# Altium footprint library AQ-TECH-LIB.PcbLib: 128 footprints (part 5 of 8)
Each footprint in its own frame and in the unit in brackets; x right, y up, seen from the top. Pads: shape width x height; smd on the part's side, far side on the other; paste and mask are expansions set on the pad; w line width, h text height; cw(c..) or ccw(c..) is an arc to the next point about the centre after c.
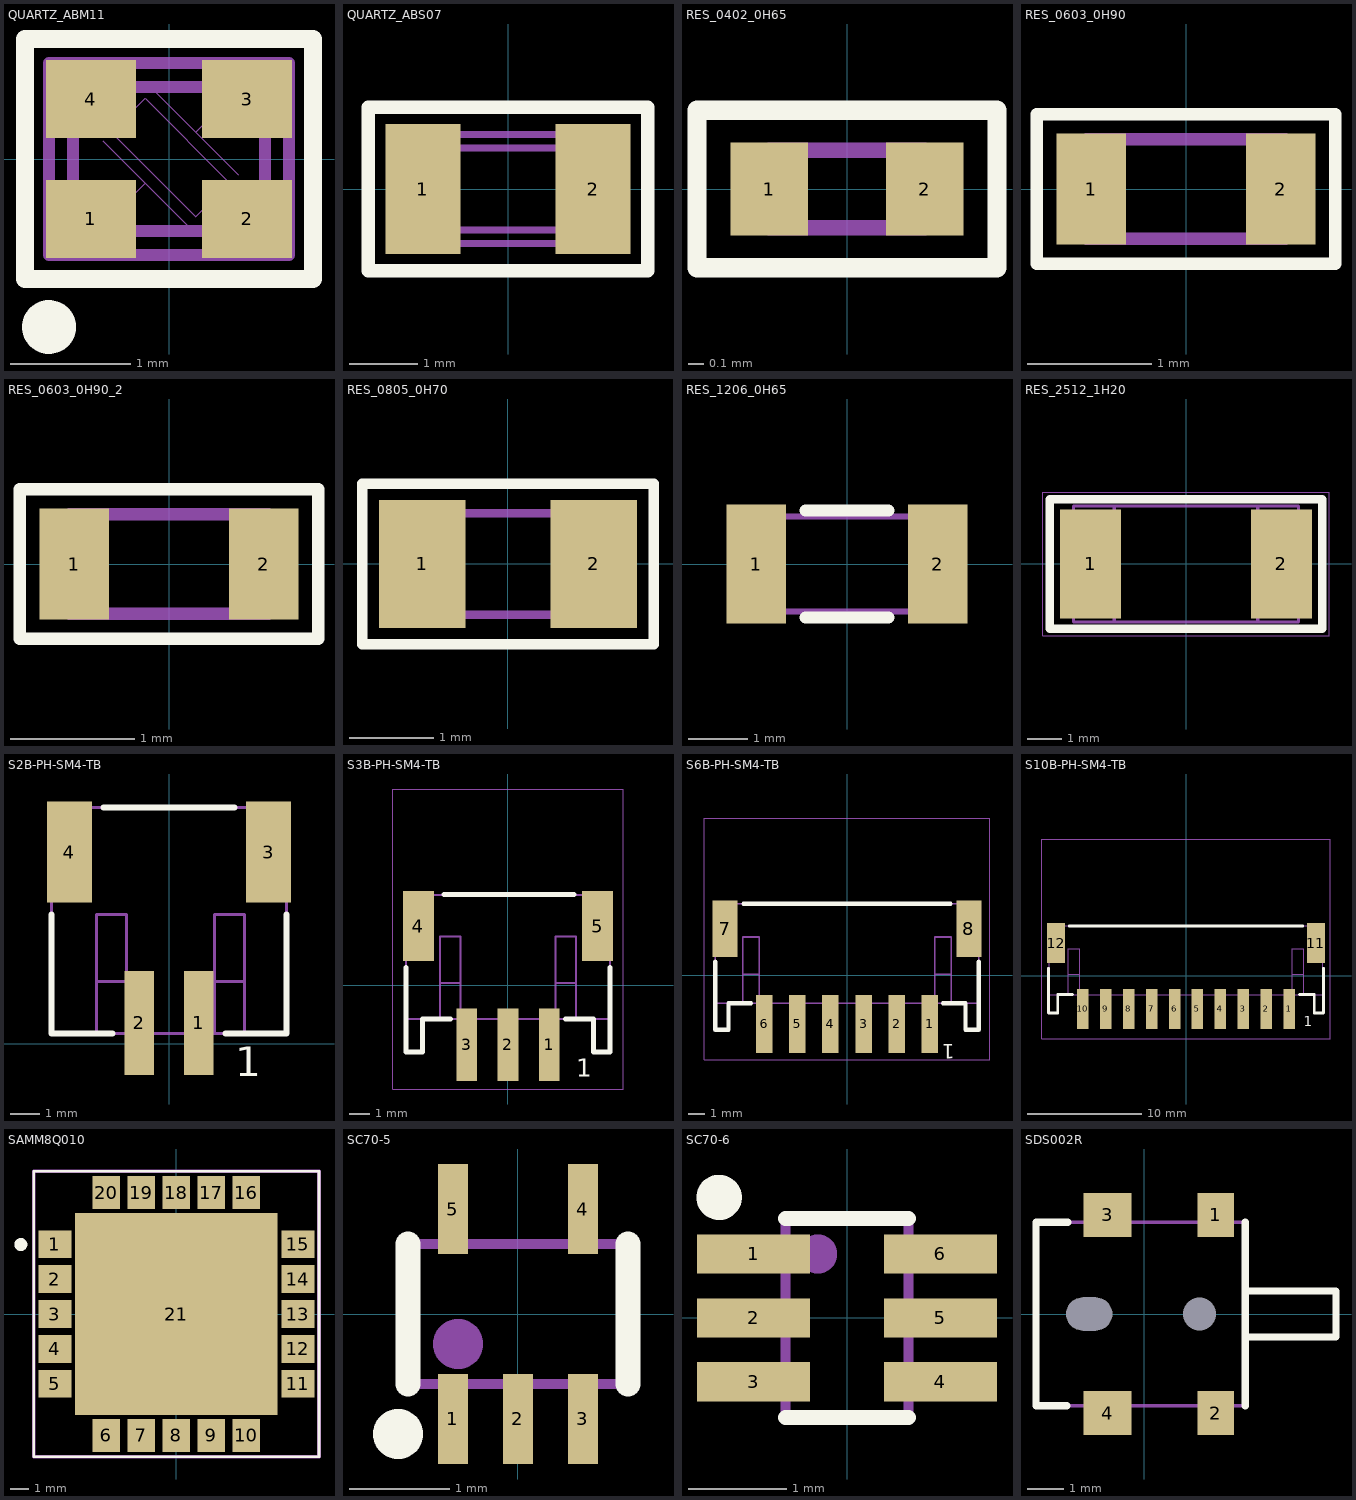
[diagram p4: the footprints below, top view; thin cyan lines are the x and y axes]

## QUARTZ_ABM11 [mm]
height 0.6
pads (4):
  rect 0.75x0.65 smd paste+0 mask+0.1: 1(-0.65,-0.5) 2(0.65,-0.5) 3(0.65,0.5) 4(-0.65,0.5)
Top Overlay:
  circle w0.25: c-1,-1.4 r0.1
  lines w0.15: -1.2,-1 1.2,-1 1.2,1 -1.2,1 -1.2,-1
Mechanical 3:
  lines w0.01: -0.554,-0.554 -0.2,-0.2 ; -0.554,0.154 0.154,-0.554 ; -0.129,0.578 0.578,-0.129 ; 0.224,0.224 0.578,0.578 ; -0.483,0.224 -0.2,0.507 0.507,-0.2 0.224,-0.483 -0.483,0.224
  lines w0.1: -1,-0.8 1,-0.8 1,0.8 -1,0.8 -1,-0.8 ; -0.8,-0.6 0.8,-0.6 0.8,0.6 -0.8,0.6 -0.8,-0.6
  text ".Designator" at -0.6,-0.1 h0.84
3D body "ABM11.STEP": height 0.59, standoff 0, extent -1.003,-0.8 1.003,0.8

## QUARTZ_ABS07 [mm]
height 0.9
pads (2):
  rect 1.1x1.9 smd paste+0 mask+0.1: 1(-1.25,0) 2(1.25,0)
Top Overlay:
  lines w0.2: -2.05,-1.2 2.05,-1.2 2.05,1.2 -2.05,1.2 -2.05,-1.2
Mechanical 3:
  lines w0.1: -1.6,-0.6 cw(c-1.55,-0.75) -1.4,-0.8 1.4,-0.8 cw(c1.55,-0.75) 1.6,-0.6 1.6,0.6 cw(c1.55,0.75) 1.4,0.8 -1.4,0.8 cw(c-1.55,0.75) -1.6,0.6 -1.6,-0.6 ; -1.4,-0.3 ccw(c-1.1,-0.3) -1.1,-0.6 1.1,-0.6 ccw(c1.1,-0.3) 1.4,-0.3 1.4,0.3 ccw(c1.1,0.3) 1.1,0.6 -1.1,0.6 ccw(c-1.1,0.3) -1.4,0.3 -1.4,-0.3
  text ".Designator" at -0.775,-0.15 h0.84
3D body "ABS07.STEP": height 0.89, standoff 0, extent -1.6,-0.749 1.6,0.749

## RES_0402_0H65 [mm]
height 0.65
pads (2):
  rect 0.5x0.6 smd: 1(-0.5,0) 2(0.5,0)
Top Overlay:
  lines w0.125: -0.965,-0.508 0.965,-0.508 0.965,0.508 -0.965,0.508 -0.965,-0.508
Mechanical 3:
  lines w0.1: -0.5,-0.25 -0.5,0.25 0.5,0.25 0.5,-0.25 -0.5,-0.25
  text "'.Designator'" at -0.965,0.508 h1
3D body: height 0.65, standoff 0, extent -0.5,-0.25 0.5,0.25

## RES_0603_0H90 [mil]
height 35.43
pads (2):
  rect 22x35 smd: 1(-30,0) 2(30,0)
Top Overlay:
  lines w3.94: -47.24,-23.62 -47.24,23.62 47.24,23.62 47.24,-23.62 -47.24,-23.62
Mechanical 3:
  lines w3.94: -31.5,-15.75 31.5,-15.75 31.5,15.75 -31.5,15.75 -31.5,-15.75
  text "'.Designator'" at 137.8,15.75 h31.5
3D body: height 35.43, standoff 0, extent -31.5,-15.75 31.5,15.75

## RES_0603_0H90_2 [mil]
pads (2):
  rect 22x35 smd: 1(-30,0) 2(30,0)
Top Overlay:
  lines w3.94: -47.24,-23.62 -47.24,23.62 47.24,23.62 47.24,-23.62 -47.24,-23.62
Mechanical 3:
  lines w3.94: -31.5,-15.75 31.5,-15.75 31.5,15.75 -31.5,15.75 -31.5,-15.75
  text "'.Designator'" at -90.55,-3.94 h23.62
3D body: height 35.43, standoff 0, extent -31.5,-15.75 31.5,15.75

## RES_0805_0H70 [mm] "refusion"
height 0.7
pads (2):
  rect 1.02x1.52 smd: 1(-1.016,0) 2(1.016,0)
Top Overlay:
  lines w0.125: -1.725,-0.95 -1.725,0.95 1.725,0.95 1.725,-0.95 -1.725,-0.95
Mechanical 3:
  lines w0.1: -1,-0.6 -1,0.6 1,0.6 1,-0.6 -1,-0.6
  text ".Designator" at -0.7,-0.4 h0.84
3D body: height 0.7, standoff 0, extent -1.525,-0.7 1.475,0.725

## RES_1206_0H65 [mm] "refusion"
height 0.65
pads (2):
  rect 1x2 smd paste+0 mask+0.1: 1(-1.524,0) 2(1.524,0)
Top Overlay:
  lines w0.2: -0.7,-0.9 0.7,-0.9 ; -0.7,0.9 0.7,0.9
Mechanical 3:
  lines w0.1: -1.6,-0.8 1.6,-0.8 1.6,0.8 -1.6,0.8 -1.6,-0.8
  text ".Designator" at -1,-0.375 h0.84
3D body: height 0.65, standoff 0, extent -1.75,-0.9 1.75,0.9

## RES_2512_1H20 [mm]
height 1.2
pads (2):
  rect 1.8x3.2 smd paste+0 mask+0.1: 1(-2.8,0) 2(2.8,0)
Top Overlay:
  lines w0.25: -4,-1.9 -4,1.9 4,1.9 4,-1.9 -4,-1.9
Mechanical 2:
  lines w0.01: -4.2,-2.1 -4.2,2.1 4.2,2.1 4.2,-2.1 -4.2,-2.1
Mechanical 3:
  lines w0.1: -3.3,-1.7 -3.3,1.7 ; -3.3,-1.7 -2.1,-1.7 -2.1,1.7 -3.3,1.7 ; -3.3,-1.7 -3.3,1.7 ; -3.3,-1.7 3.3,-1.7 ; -3.3,1.7 3.3,1.7 ; 3.3,-1.7 2.1,-1.7 2.1,1.7 3.3,1.7 ; 3.3,-1.7 3.3,1.7 ; 3.3,-1.7 3.3,1.7
  text ".Designator" at 0.45,0.375 h0.84
3D body: height 1.2, standoff 0, extent -3.3,-1.7 -2.1,1.7
3D body: height 1.2, standoff 0, extent -2.1,-1.7 2.1,1.7
3D body: height 1.2, standoff 0, extent 2.1,-1.7 3.3,1.7

## S2B-PH-SM4-TB [mm]
height 5.5
pads (4):
  rect 1x3.5 smd: 1(1,0.7) 2(-1,0.7)
  rect 1.5x3.4 smd: 3(3.35,6.45) 4(-3.35,6.45)
Top Overlay:
  lines w0.2: -3.95,4.35 -3.95,0.35 -1.9,0.35 ; -2.2,7.95 2.2,7.95 ; 1.9,0.35 3.95,0.35 3.95,4.35
  text "1" at 2.225,-1.1 h1
Mechanical 3:
  lines w0.1: -2.435,0.35 -2.435,4.35 -1.435,4.35 -1.435,0.35 ; -2.435,2.1 -1.435,2.1 ; 1.539,0.35 1.539,4.35 2.539,4.35 2.539,0.35 ; 1.539,2.1 2.539,2.1 ; -3.95,0.35 -3.95,7.95 3.95,7.95 3.95,0.35 -3.95,0.35
  text "1" at 3.075,0.725 h0.84
  text ".Designator" at -0.05,2.825 h0.84
3D body "S2B-PH-SM4-TB(LF)(SN)--3DModel-STEP-56544.STEP": height 5.58, standoff -0.02, extent -3.95,-0.65 3.95,7.95

## S3B-PH-SM4-TB [mm]
height 5.7
pads (5):
  rect 1x3.5 smd mask+0.1: 1(2,-2.875) 2(0,-2.875) 3(-2,-2.875)
  rect 1.5x3.4 smd mask+0.1: 4(-4.35,2.875) 5(4.35,2.875)
Top Overlay:
  lines w0.25: -4.95,0.875 -4.95,-3.225 -4.15,-3.225 -4.15,-1.625 -2.8,-1.625 ; -3.1,4.4 3.2,4.4 ; 2.8,-1.625 4.15,-1.625 4.15,-3.225 4.95,-3.225 4.95,0.875
  text "1" at 3.3,-4.725 h1.5
Mechanical 1:
  lines w0.01: -5.6,-5.025 5.6,-5.025 5.6,9.525 -5.6,9.525 -5.6,-5.025
Mechanical 3:
  lines w0.1: -4.45,3.575 -4.45,4.375 ; -4.15,-1.625 -4.15,-3.225 -4.95,-3.225 -4.95,-1.625 ; -3.3,0.125 -2.3,0.125 ; -0.25,-2.125 0.25,-2.125 ; -0.25,-1.625 -0.25,-2.225 ; 0.25,-1.625 0.25,-2.225 ; 1.75,-2.125 2.25,-2.125 ; 1.75,-1.625 1.75,-2.225 ; 2.25,-1.625 2.25,-2.225 ; 2.3,0.125 3.3,0.125 ; 4.15,-1.625 4.15,-3.225 4.95,-3.225 4.95,-1.625 ; 4.45,3.575 4.45,4.375 4.05,4.375 ; -4.95,-1.625 2.3,-1.625 ; -4.95,-1.625 -4.95,3.575 -4.05,3.575 -4.05,4.375 -4.45,4.375 ; -4.95,-1.625 -3.3,-1.625 ; -4.45,4.375 4.05,4.375 ; -3.3,-1.625 -2.3,-1.625 -2.3,2.375 -3.3,2.375 -3.3,-1.625 ; -2.25,-4.225 -2.25,-2.225 ; -2.25,-4.225 -1.75,-4.225 ; -2.25,-4.225 -1.75,-4.225 ; -2.25,-4.225 -2.25,-2.225 ; -2.25,-2.225 -1.75,-2.225 ; -2.25,-2.225 -1.75,-2.225 ; -2.25,-2.225 -2.25,-1.625 -2.25,-2.125 ; -2.25,-2.225 -2.25,-2.125 ; -2.25,-2.125 -1.75,-2.125 ; -2.25,-2.125 -1.75,-2.125 ; -1.75,-4.225 -1.75,-2.225 ; -1.75,-4.225 -1.75,-2.225 ; -1.75,-2.225 -1.75,-1.625 -1.75,-2.125 ; -1.75,-2.225 -1.75,-2.125 ; -0.25,-2.225 0.25,-2.225 ; -0.25,-2.225 -0.25,-4.225 0.25,-4.225 0.25,-2.225 ; 1.75,-2.225 2.25,-2.225 ; 1.75,-2.225 1.75,-4.225 2.25,-4.225 2.25,-2.225 ; 2.3,-1.625 3.3,-1.625 ; 2.3,-1.625 2.3,2.375 3.3,2.375 3.3,-1.625 ; 3.3,-1.625 4.95,-1.625 ; 4.05,4.375 4.05,3.575 4.95,3.575 4.95,-1.625
  text ".Designator" at 0,0 h0.84
  text "1" at 1.5,-1.375 h0.84
  text "3" at -1.9,-1.325 h0.84
3D body "S3B-PH-SM4-TB.STEP": height 5.6, standoff 0, extent -4.95,-4.225 4.95,4.375

## S6B-PH-SM4-TB [mm]
height 5.7
pads (8):
  rect 1x3.5 smd mask+0.1: 1(5,-2.95) 2(3,-2.95) 3(1,-2.95) 4(-1,-2.95) 5(-3,-2.95) 6(-5,-2.95)
  rect 1.5x3.4 smd mask+0.1: 7(-7.35,2.8) 8(7.35,2.8)
Top Overlay:
  lines w0.25: -7.95,0.8 -7.95,-3.3 -7.15,-3.3 -7.15,-1.7 -5.8,-1.7 ; -6.25,4.3 6.25,4.3 ; 5.8,-1.7 7.15,-1.7 7.15,-3.3 7.95,-3.3 7.95,0.8
  text "1" at 6.5,-3.884 h1.5
Mechanical 1:
  lines w0.01: -8.6,-5.1 8.6,-5.1 8.6,9.45 -8.6,9.45 -8.6,-5.1
Mechanical 3:
  lines w0.1: -7.45,3.5 -7.45,4.3 -7.05,4.3 ; -7.15,-1.7 -7.15,-3.3 -7.95,-3.3 -7.95,-1.7 ; -6.3,0.05 -5.3,0.05 ; -5.25,-1.7 -5.25,-2.2 ; -4.75,-1.7 -4.75,-2.2 ; -3.25,-2.2 -2.75,-2.2 ; -3.25,-1.7 -3.25,-2.3 ; -2.75,-1.7 -2.75,-2.3 ; -1.25,-2.2 -0.75,-2.2 ; -1.25,-1.7 -1.25,-2.3 ; -0.75,-1.7 -0.75,-2.3 ; 0.75,-2.2 1.25,-2.2 ; 0.75,-1.7 0.75,-2.3 ; 1.25,-1.7 1.25,-2.3 ; 2.75,-2.2 3.25,-2.2 ; 2.75,-1.7 2.75,-2.3 ; 3.25,-1.7 3.25,-2.3 ; 4.75,-2.2 5.25,-2.2 ; 4.75,-1.7 4.75,-2.3 ; 5.25,-1.7 5.25,-2.3 ; 5.3,0.05 6.3,0.05 ; 7.15,-1.7 7.15,-3.3 7.95,-3.3 7.95,-1.7 ; 7.45,3.5 7.45,4.3 7.05,4.3 ; -7.95,-1.7 -7.95,3.5 -7.05,3.5 -7.05,4.3 ; -7.95,-1.7 -6.3,-1.7 ; -7.05,4.3 7.05,4.3 ; -6.3,-1.7 -6.3,2.3 -5.3,2.3 -5.3,-1.7 ; -6.3,-1.7 -5.3,-1.7 ; -5.3,-1.7 5.3,-1.7 ; -5.25,-2.3 -4.75,-2.3 ; -5.25,-2.3 -5.25,-4.3 -4.75,-4.3 -4.75,-2.3 ; -5.25,-2.3 -5.25,-2.2 ; -5.25,-2.2 -4.75,-2.2 ; -4.75,-2.3 -4.75,-2.2 ; -3.25,-2.3 -3.25,-4.3 -2.75,-4.3 -2.75,-2.3 ; -3.25,-2.3 -2.75,-2.3 ; -1.25,-2.3 -0.75,-2.3 ; -1.25,-2.3 -1.25,-4.3 -0.75,-4.3 -0.75,-2.3 ; 0.75,-2.3 1.25,-2.3 ; 0.75,-2.3 0.75,-4.3 1.25,-4.3 1.25,-2.3 ; 2.75,-2.3 3.25,-2.3 ; 2.75,-2.3 2.75,-4.3 3.25,-4.3 3.25,-2.3 ; 4.75,-2.3 5.25,-2.3 ; 4.75,-2.3 4.75,-4.3 5.25,-4.3 5.25,-2.3 ; 5.3,-1.7 5.3,2.3 6.3,2.3 6.3,-1.7 ; 5.3,-1.7 6.3,-1.7 ; 6.3,-1.7 7.95,-1.7 ; 7.05,4.3 7.05,3.5 7.95,3.5 7.95,-1.7
  text ".Designator" at -0.4,1.455 h0.84
  text "1" at 4.5,-0.5 h0.84
  text "6" at -4.1,-0.3 h0.84
3D body "S6B-PH-SM4-TB.STEP": height 5.6, standoff 0, extent -7.95,-4.3 7.95,4.3

## S10B-PH-SM4-TB [mm]
height 5.7
pads (12):
  rect 1x3.5 smd mask+0.1: 1(9,-2.875) 2(7,-2.875) 3(5,-2.875) 4(3,-2.875) 5(1,-2.875) 6(-1,-2.875) 7(-3,-2.875) 8(-5,-2.875) 9(-7,-2.875) 10(-9,-2.875)
  rect 1.6x3.5 smd mask+0.1: 11(11.35,2.875) 12(-11.35,2.875)
Top Overlay:
  lines w0.25: -12,0.675 -12,-3.225 -11.2,-3.225 -11.2,-1.625 -9.9,-1.625 ; -10.2,4.375 10.2,4.375 ; 9.9,-1.625 11.2,-1.625 11.2,-3.225 12,-3.225 12,0.675
  text "1" at 10.3,-4.7 h1.5
Mechanical 1:
  lines w0.01: -12.6,-5.475 12.6,-5.475 12.6,11.925 -12.6,11.925 -12.6,-5.475
Mechanical 3:
  lines w0.1: -11.45,3.575 -11.45,4.375 -11.05,4.375 ; -11.15,-1.625 -11.15,-3.225 -11.95,-3.225 -11.95,-1.625 ; -10.3,0.125 -9.3,0.125 ; -9.25,-1.625 -9.25,-2.125 ; -8.75,-1.625 -8.75,-2.125 ; -7.25,-1.625 -7.25,-2.125 ; -6.75,-1.625 -6.75,-2.125 ; -5.25,-1.625 -5.25,-2.125 ; -4.75,-1.625 -4.75,-2.125 ; -3.25,-1.625 -3.25,-2.125 ; -2.75,-1.625 -2.75,-2.125 ; -0.75,-1.625 -0.75,-2.125 ; 0.75,-2.125 1.25,-2.125 ; 0.75,-1.625 0.75,-2.225 ; 1.25,-1.625 1.25,-2.225 ; 2.75,-2.125 3.25,-2.125 ; 2.75,-1.625 2.75,-2.225 ; 3.25,-1.625 3.25,-2.225 ; 4.75,-2.125 5.25,-2.125 ; 4.75,-1.625 4.75,-2.225 ; 5.25,-1.625 5.25,-2.225 ; 6.75,-2.125 7.25,-2.125 ; 6.75,-1.625 6.75,-2.225 ; 7.25,-1.625 7.25,-2.225 ; 8.75,-2.125 9.25,-2.125 ; 8.75,-1.625 8.75,-2.225 ; 9.25,-1.625 9.25,-2.225 ; 9.3,0.125 10.3,0.125 ; 11.15,-1.625 11.15,-3.225 11.95,-3.225 11.95,-1.625 ; 11.45,3.575 11.45,4.375 11.05,4.375 ; -11.95,-1.625 -11.95,3.575 -11.05,3.575 -11.05,4.375 ; -11.95,-1.625 -10.3,-1.625 ; -11.05,4.375 11.05,4.375 ; -10.3,-1.625 -10.3,2.375 -9.3,2.375 -9.3,-1.625 ; -10.3,-1.625 -9.3,-1.625 ; -9.3,-1.625 -1.25,-1.625 ; -9.25,-2.225 -9.25,-2.125 ; -9.25,-2.225 -8.75,-2.225 ; -9.25,-2.225 -9.25,-4.225 -8.75,-4.225 -8.75,-2.225 ; -9.25,-2.125 -8.75,-2.125 ; -8.75,-2.225 -8.75,-2.125 ; -7.25,-2.225 -6.75,-2.225 ; -7.25,-2.225 -7.25,-2.125 ; -7.25,-2.225 -7.25,-4.225 -6.75,-4.225 -6.75,-2.225 ; -7.25,-2.125 -6.75,-2.125 ; -6.75,-2.225 -6.75,-2.125 ; -5.25,-2.225 -5.25,-2.125 ; -5.25,-2.225 -4.75,-2.225 ; -5.25,-2.225 -5.25,-4.225 -4.75,-4.225 -4.75,-2.225 ; -5.25,-2.125 -4.75,-2.125 ; -4.75,-2.225 -4.75,-2.125 ; -3.25,-2.225 -2.75,-2.225 ; -3.25,-2.225 -3.25,-2.125 ; -3.25,-2.225 -3.25,-4.225 -2.75,-4.225 -2.75,-2.225 ; -3.25,-2.125 -2.75,-2.125 ; -2.75,-2.225 -2.75,-2.125 ; -1.25,-2.225 -0.75,-2.225 ; -1.25,-2.225 -1.25,-2.125 ; -1.25,-2.225 -1.25,-4.225 -0.75,-4.225 -0.75,-2.225 ; -1.25,-2.125 -1.25,-1.625 ; -1.25,-2.125 -0.75,-2.125 ; -1.25,-1.625 9.3,-1.625 ; -0.75,-2.225 -0.75,-2.125 ; 0.75,-2.225 1.25,-2.225 ; 0.75,-2.225 0.75,-4.225 1.25,-4.225 1.25,-2.225 ; 2.75,-2.225 3.25,-2.225 ; 2.75,-2.225 2.75,-4.225 3.25,-4.225 3.25,-2.225 ; 4.75,-2.225 5.25,-2.225 ; 4.75,-2.225 4.75,-4.225 5.25,-4.225 5.25,-2.225 ; 6.75,-2.225 7.25,-2.225 ; 6.75,-2.225 6.75,-4.225 7.25,-4.225 7.25,-2.225 ; 8.75,-2.225 9.25,-2.225 ; 8.75,-2.225 8.75,-4.225 9.25,-4.225 9.25,-2.225 ; 9.3,-1.625 9.3,2.375 10.3,2.375 10.3,-1.625 ; 9.3,-1.625 10.3,-1.625 ; 10.3,-1.625 11.95,-1.625 ; 11.05,4.375 11.05,3.575 11.95,3.575 11.95,-1.625
  text "1" at 8.5,-1.375 h0.84
  text ".Designator" at 0,0 h0.84
  text "10" at -9,-1.075 h0.84
3D body "S10B-PH-SM4-TB.STEP": height 5.6, standoff 0, extent -11.95,-4.225 11.95,4.375

## SAMM8Q010 [mm]
pads (21):
  rect 1.8x1.5 smd mask+0.05: 1(-6.6,3.8) 2(-6.6,1.9) 3(-6.6,0) 4(-6.6,-1.9) 5(-6.6,-3.8) 11(6.6,-3.8) 12(6.6,-1.9) 13(6.6,0) 14(6.6,1.9) 15(6.6,3.8)
  rect 1.5x1.8 smd mask+0.05: 6(-3.8,-6.6) 7(-1.9,-6.6) 8(0,-6.6) 9(1.9,-6.6) 10(3.8,-6.6) 16(3.8,6.6) 17(1.9,6.6) 18(0,6.6) 19(-1.9,6.6) 20(-3.8,6.6)
  rect 11x11 smd mask+0.05: 21(0,0)
Top Overlay:
  circle w0.5: c-8.45,3.775 r0.1
  lines w0.15: -7.75,-7.75 7.75,-7.75 7.75,7.75 -7.75,7.75 -7.75,-7.75
Mechanical 3:
  circle w0.3: c-4.25,3.75 r0.618
  lines w0.2: -7.75,-7.75 -7.75,7.75 7.75,7.75 7.75,-7.75 -7.75,-7.75
  text ".Designator" at 0,0 h0.84
3D body "SAM-M8Q-0-10.stp": height 3.1, standoff 0, extent -7.75,-7.75 7.75,7.75

## SC70-5 [mm]
height 1.1
pads (5):
  rect 0.3x0.9 smd paste+0 mask+0.1: 1(-0.65,-1.05) 2(0,-1.05) 3(0.65,-1.05) 4(0.65,1.05) 5(-0.65,1.05)
Top Overlay:
  circle w0.3: c-1.2,-1.2 r0.1
  lines w0.25: -1.1,-0.7 -1.1,0.7 ; 1.1,-0.7 1.1,0.7
Mechanical 3:
  circle w0.3: c-0.6,-0.3 r0.1
  lines w0.1: -1.1,-0.7 -1.1,0.7 1.1,0.7 1.1,-0.7 -1.1,-0.7
  text ".Designator" at 0,0 h0.84
3D body "Conception1.stp": height 1.1, standoff 0, extent -1,-1.1 1,1.1

## SC70-6 [mm] "SC70-6"
height 1.1
pads (6):
  rect 1.15x0.4 smd mask+0.05: 1(-0.95,0.65) 2(-0.95,0) 3(-0.95,-0.65) 4(0.95,-0.65) 5(0.95,0) 6(0.95,0.65)
Top Overlay:
  circle w0.3: c-1.3,1.225 r0.08
  lines w0.15: -0.625,-1.012 0.625,-1.012 ; -0.625,1.012 0.625,1.012
Mechanical 3:
  circle w0.2: c-0.3,0.65 r0.1
  lines w0.1: -0.625,-1.012 0.625,-1.012 0.625,1.012 -0.625,1.012 -0.625,-1.012
  text ".Designator" at 0,0 h0.84
3D body "MIC94092YC6_TR.stp": height 1.1, standoff 0, extent -1.05,-1.012 1.05,1.012

## SDS002R [mm]
height 2
pads (6):
  round 0 hole 0.9 slot 1.25 at 0 deg unplated paste+0 mask+0.1: 0(-1.5,0)
  round 0 hole 0.9 unplated paste+0 mask+0.1: 0(1.5,0)
  rect 1x1.2 smd: 1(1.95,2.7) 2(1.95,-2.7)
  rect 1.3x1.2 smd: 3(-1,2.7) 4(-1,-2.7)
Top Overlay:
  lines w0.2: -2.106,-2.5 -2.95,-2.5 -2.95,2.5 -2.088,2.5 ; 2.75,-2.5 2.75,2.5 ; 2.75,-0.625 5.225,-0.625 5.225,0.625 2.75,0.625
Mechanical 3:
  lines w0.1: 2.75,-0.625 5.225,-0.625 5.225,0.625 2.75,0.625 ; -2.95,-2.5 -2.95,2.5 2.75,2.5 2.75,-2.5 -2.95,-2.5
  text "'.Designator'" at 0,0 h1
3D body "SDS002R.stp": height 2, standoff -0.6, extent -2.95,-2.5 5.25,2.5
